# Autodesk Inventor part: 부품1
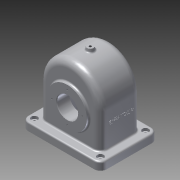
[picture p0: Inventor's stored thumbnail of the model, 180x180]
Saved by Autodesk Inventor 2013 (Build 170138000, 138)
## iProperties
Created: 2016-10
Part Number: 부품1
Material: 알루미늄 6061
Document SubType Name: Modeling
Designer: cad10
Density: 2.40731 g/cm^3
Mass: 1034.45 g
Surface Area: 1200.62 cm^2
Volume: 429.71 cm^3
Author: cad10
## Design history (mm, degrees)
sketch "스케치2"
  geometry: L1 (-58, 0)-(58, 0); L2 (58, 0)-(58, -65); L3 (58, -65)-(-58, -65); L4 (-58, -65)-(-58, 0); A1 r 58 centre (0, 0) between (58, 0) and (-58, 0); 1 further point
  constraints: 8 end point, 2 parallel, 2 point on circle, 2 tangent, 1 centre point, 1 coincident, 1 horizontal, 1 perpendicular
  dimensions: "d0" = 65 distance of L3.end L1.start; "d2" = 58 radius of A1
extrude "돌출1" new body sketch "스케치2" distance "d3" = 77; taper "d4" = 0 deg
sketch "스케치3"
  geometry: L1 (116, 0)-(0, 0) reference; L2 (0, 77)-(116, 77) reference; L3 (0, 0)-(0, 77) reference; L4 (-17, 93.5)-(133, 93.5); L5 (133, 93.5)-(133, -16.5); L6 (133, -16.5)-(-17, -16.5); L7 (-17, -16.5)-(-17, 93.5); 1 further point
  constraints: 8 end point, 2 parallel, 1 horizontal, 1 perpendicular
  dimensions: "d5" = 110 distance of L6.end L4.start; "d7" = 150 distance of L4.start L4.end; "d8" = 77 distance between parallel lines of L1 L2 (derived); "d9" = 16.5 distance between parallel lines of L2 L4; "d10" = 17 distance between parallel lines of L3 L7
extrude "돌출2" join sketch "스케치3" distance "d11" = 15; taper "d12" = 0 deg
node "작업 평면1"
sketch "스케치6"
  geometry: L1 (116, 77)-(0, 77) reference; 2 further points
  dimensions: "d16" = 38.5 distance from line of L1 point (58, 38.5); "d17" = 0 horizontal distance of point (58, 0) point (58, 38.5)
hole "구멍1" sketch "스케치6" at (58, 38.5) diameter "d18" = 4.459; stored, may be unused: countersink angle "d22" = 90 deg, drill point angle "d24" = 118 deg; dims "d19" = 10, "d20" = 4, "d21" = 2, "d23" = 46.25
fillet "모깎기1" dims "d25" = 3
fillet "모깎기2" dims "d26" = 12
sketch "스케치7"
  geometry: A1 r 9 centre (-5, -81.5) between (-14, -81.5) and (-5, -90.5) reference; A2 r 9 centre (121, -81.5) between (121, -90.5) and (130, -81.5) reference; A3 r 9 centre (121, 4.5) between (130, 4.5) and (121, 13.5) reference; A4 r 9 centre (-5, 4.5) between (-5, 13.5) and (-14, 4.5) reference; 1 further point
hole "구멍2" sketch "스케치7" at (-5, -81.5), (121, -81.5), (121, 4.5), (-5, 4.5) diameter "d27" = 5; stored, may be unused: countersink angle "d31" = 90 deg, drill point angle "d33" = 118 deg; dims "d28" = 10, "d29" = 12, "d30" = 5, "d32" = 46.25
sketch "스케치8"
  geometry: L1 (63, -80)-(-63, -80) reference; C1 r 37.5 at (0, -15); A1 r 58 centre (0, 0) between (58, 0) and (-58, 0) reference
  constraints: 1 centre point, 1 vertical alignment
  dimensions: "d34" = 65 distance from line of L1 C1.centre; "d35" = 75 diameter of C1
extrude "돌출3" join sketch "스케치8" distance "d36" = 5; taper "d37" = 0 deg
sketch "스케치9"
  geometry: L1 (63, -80)-(-63, -80) reference; C1 r 31 at (0, -15); A1 r 58 centre (0, 0) between (58, 0) and (-58, 0) reference
  constraints: 1 centre point, 1 vertical alignment
  dimensions: "d38" = 65 distance from line of L1 C1.centre; "d39" = 62 diameter of C1
extrude "돌출4" join sketch "스케치9" distance "d40" = 10; taper "d41" = 0 deg
sketch "스케치10"
  geometry: C1 r 37.5 at (0, 0) reference; C2 r 20 at (0, 0); 1 further point
  constraints: 1 centre point, 1 coincident
  dimensions: "d42" = 40 diameter of C2
extrude "돌출5" cut sketch "스케치10" stored distance "d44" = 10; taper "d45" = 0 deg
fillet "모깎기3" dims "d49" = 13
sketch "스케치14"
  geometry: L1 (-17, -4.5)-(-17, 81.5) reference; C1 r 6 at (58, 38); 1 further point
  constraints: 1 centre point
  dimensions: "d50" = 38 distance of C1.centre point (58, 0); "d51" = 75 distance from line of L1 C1.centre; "d52" = 12 diameter of C1
extrude "돌출6" join sketch "스케치14" stored distance "d53" = 10; taper "d54" = 10 deg
sketch "스케치15"
  geometry: C1 r 6 at (0, 0) reference; 2 further points
  constraints: 1 coincident
hole "구멍3" sketch "스케치15" at (0, 0) diameter "d55" = 4.459; stored, may be unused: countersink angle "d59" = 90 deg, drill point angle "d61" = 118 deg; dims "d56" = 6, "d57" = 4, "d58" = 2, "d60" = 8
sketch "스케치17" dims "d67" = 58
  geometry: C1 r 20 at (0, 0) reference; C2 r 37.5 at (0, 0) reference; 3 further points
  constraints: 2 horizontal alignment, 1 coincident, 2 other
hole "구멍4" sketch "스케치17" at (-29, 0) diameter "d69" = 2.459; stored, may be unused: countersink angle "d73" = 90 deg, drill point angle "d75" = 118 deg; dims "d70" = 6, "d71" = 4, "d72" = 2, "d74" = 8
sketch "스케치18" dims "d79" = 52
  geometry: C1 r 20 at (0, 0) reference; C2 r 31 at (0, 0) reference; 3 further points
  constraints: 2 vertical alignment, 1 coincident, 2 other
hole "구멍5" sketch "스케치18" at (0, 26) diameter "d81" = 2.459; stored, may be unused: countersink angle "d85" = 90 deg, drill point angle "d87" = 118 deg; dims "d82" = 6, "d83" = 4, "d84" = 2, "d86" = 8
node "작업 평면3"
sketch "스케치20"
  geometry: L1 (-63, -65)-(63, -65) reference; L2 (-58, -50)-(-58, 15) reference; C1 r 28 at (0, 0); 1 further point
  constraints: 1 centre point
  dimensions: "d94" = 56 diameter of C1; "d96" = 65 distance from line of L1 C1.centre; "d97" = 58 distance from line of L2 C1.centre
extrude "돌출7" cut sketch "스케치20" distance "d98" = 53; taper "d99" = 0 deg
sketch "스케치22"
  geometry: L1 (-52, 15)-(52, 15); L2 (52, 15)-(52, -65); L3 (52, -65)-(-52, -65); L4 (-52, -65)-(-52, 15); L5 (-63, -65)-(63, -65) reference; A1 r 52 centre (0, 15) between (52, 15) and (-52, 15); 1 further point
  constraints: 8 end point, 2 parallel, 2 point on circle, 1 centre point, 1 coincident, 1 horizontal, 1 perpendicular, 1 point on line, 1 tangent
  dimensions: "d100" = 104 diameter of A1
extrude "돌출8" cut sketch "스케치22" distance "d103" = 67; taper "d104" = 0 deg
chamfer "모따기1" distance "d105" = 1; stored, may be unused: second distance "d106" = 2, angle "d107" = 45 deg
sketch "스케치23"
  geometry: L1 (13, 58)-(24.747, 72); L2 (-15, 90.791)-(-15, -25.793); L3 (-80, 5)-(-80, 72) reference; L4 (-80, 72)-(0, 72) reference; L5 (13, 58)-(-15, 58); L6 (-15, 58)-(-15, 72); L7 (-15, 72)-(24.747, 72); L8 (-15, 72)-(24.747, 72); 1 further point
  constraints: 12 end point, 3 point on line, 2 perpendicular, 1 collinear
  dimensions: "d110" = 65 distance between parallel lines of L3 L2; "d115" = 28 distance of L1.start L5.end; "d116" = 50 deg angle of L5 L1; "d117" = 14 distance between parallel lines of L4 L5
revolve "회전1" sketch "스케치23" stored, may be unused: angle "d118" = 90 deg
fillet "모깎기4" dims "d119" = 8
fillet "모깎기5" dims "d120" = 3
sketch "스케치24"
  geometry: C1 r 20 at (0, 0) reference; C2 r 20 at (0, 0); 1 further point
  constraints: 1 centre point, 1 coincident, 1 concentric
extrude "돌출9" cut sketch "스케치24" distance "d121" = 67; taper "d122" = 0 deg
fillet "모깎기6" dims "d125" = 3
node "작업 평면4"
sketch "스케치26"
  geometry: 2 further points
  constraints: 1 other
feature "엠보싱1" sketch "스케치26" dims "d129" = 0.5, "d130" = 0
fillet "모깎기7" dims "d131" = 3
node "솔리드1"
pattern_circular "원형 패턴1" dims angle "d77" = 360 deg
pattern_circular "원형 패턴2" dims angle "d89" = 360 deg
other parameters: "d13" = -144, "d126" = 15.5
